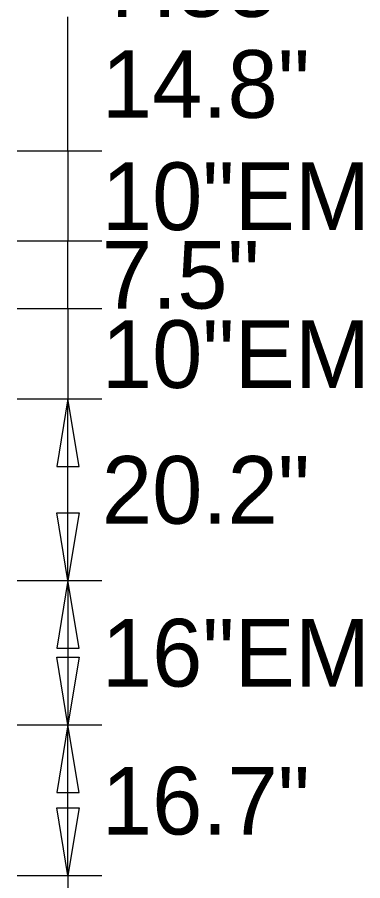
# Model space of a CAD drawing. Extents: x 1806251 to 1809821, y 414895 to 422886.
# Drawn here: x 1809678.852 to 1809679.235, y 415042.024 to 415042.982 of the extents above; entities that cross this region are included whole.
import ezdxf

# ---------------------------------------------------------------- set-up
doc = ezdxf.new("R2010")
doc.units = 0
doc.layers.add('GSDIMS', color=7, linetype='Continuous')

msp = doc.modelspace()

# ---------------------------------------------------------------- linework, layer by layer
at = {"layer": 'GSDIMS'}
for p, q in [((1809678.9085, 415042.83357), (1809678.9085, 415042.982)), ((1809678.85225, 415042.83357), (1809678.946, 415042.83357)), ((1809678.85225, 415042.83357), (1809678.946, 415042.83357)), ((1809678.9085, 415042.83357), (1809678.9085, 415042.73357)), ((1809678.85225, 415042.73357), (1809678.946, 415042.73357)), ((1809678.85225, 415042.73357), (1809678.946, 415042.73357)), ((1809678.9085, 415042.65857), (1809678.9085, 415042.73357)), ((1809678.85225, 415042.65857), (1809678.946, 415042.65857)), ((1809678.85225, 415042.65857), (1809678.946, 415042.65857)), ((1809678.9085, 415042.65857), (1809678.9085, 415042.55857)), ((1809678.85225, 415042.55857), (1809678.946, 415042.55857)), ((1809678.85225, 415042.55857), (1809678.946, 415042.55857)), ((1809678.9085, 415042.35707), (1809678.9085, 415042.55857)), ((1809678.85225, 415042.35707), (1809678.946, 415042.35707)), ((1809678.85225, 415042.35707), (1809678.946, 415042.35707)), ((1809678.9085, 415042.35707), (1809678.9085, 415042.19707)), ((1809678.85225, 415042.19707), (1809678.946, 415042.19707)), ((1809678.85225, 415042.19707), (1809678.946, 415042.19707)), ((1809678.9085, 415042.03007), (1809678.9085, 415042.19707)), ((1809678.85225, 415042.03007), (1809678.946, 415042.03007)), ((1809678.85225, 415042.03007), (1809678.946, 415042.03007)), ((1809678.9085, 415042.03007), (1809678.9085, 415041.93007))]:
    msp.add_line(p, q, dxfattribs=at)
for points in [[(1809678.9085, 415042.55857), (1809678.896, 415042.48357), (1809678.921, 415042.48357)], [(1809678.9085, 415042.35707), (1809678.896, 415042.43207), (1809678.921, 415042.43207)], [(1809678.9085, 415042.35707), (1809678.896, 415042.28207), (1809678.921, 415042.28207)], [(1809678.9085, 415042.19707), (1809678.896, 415042.27207), (1809678.921, 415042.27207)], [(1809678.9085, 415042.19707), (1809678.896, 415042.12207), (1809678.921, 415042.12207)], [(1809678.9085, 415042.03007), (1809678.896, 415042.10507), (1809678.921, 415042.10507)]]:
    msp.add_lwpolyline(points, close=True, dxfattribs=at)

# ---------------------------------------------------------------- texts
for s, p in [('7.55"', (1809678.946, 415042.982)), ('14.8"', (1809678.946, 415042.87007)), ('10"EM', (1809678.946, 415042.74565)), ('7.5"', (1809678.946, 415042.65865)), ('10"EM', (1809678.946, 415042.57065)), ('20.2"', (1809678.946, 415042.42015)), ('16"EM', (1809678.946, 415042.23965)), ('16.7"', (1809678.946, 415042.07565))]:
    msp.add_text(s, height=0.075, dxfattribs=at).set_placement(p)

doc.saveas('drawing.dxf')
